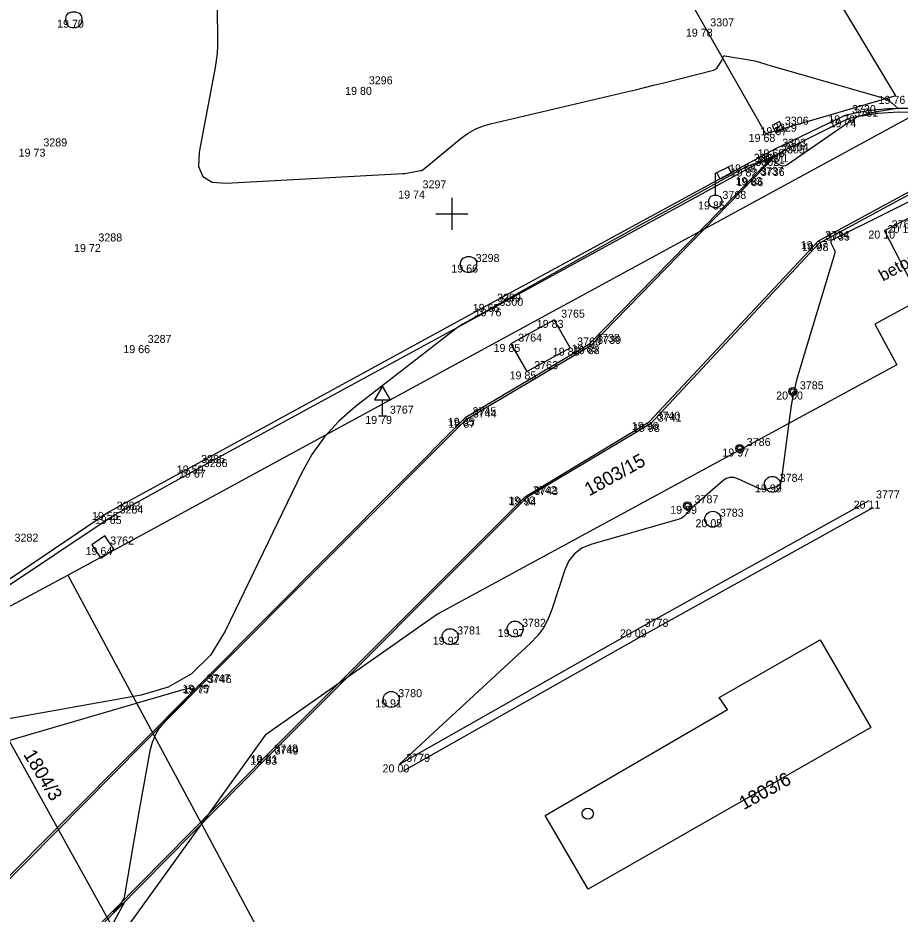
# Model space of a CAD drawing. Extents: x -702257 to -701487, y -1009871 to -1008841.
# Drawn here: x -702113.55 to -702085.99, y -1009721.88 to -1009693.87 of the extents above; entities that cross this region are included whole.
import ezdxf

# ---------------------------------------------------------------- set-up
doc = ezdxf.new("R2010")
doc.units = 0
for name, color, linetype in [('Ex_Major Contours', 7, 'Continuous'), ('Ex_Minor Contours', 7, 'Continuous'), ('Z_betonova_konstrukce', 7, 'Continuous'), ('Z_body', 7, 'Continuous'), ('Z_body_cisla', 7, 'Continuous'), ('Z_body_vysky_redukovane', 7, 'Continuous'), ('Z_dopravni_znacky', 7, 'Continuous'), ('Z_hektometricka_sit', 7, 'Continuous'), ('Z_katastr_cisla_pozemkova', 7, 'Continuous'), ('Z_katastr_cisla_stavebni', 7, 'Continuous'), ('Z_katastr_hranice', 7, 'Continuous'), ('Z_katastr_znacky_budov', 7, 'Continuous'), ('Z_komunikace', 7, 'Continuous'), ('Z_obruba', 7, 'Continuous'), ('Z_ploty', 7, 'Continuous'), ('Z_popisy', 7, 'Continuous'), ('Z_rozhranni', 7, 'Continuous'), ('Z_site_kanalizace_znaky', 7, 'Continuous'), ('Z_site_nerozlisene_znaky', 7, 'Continuous'), ('Z_site_vo_znaky', 7, 'Continuous'), ('Z_sloupek_kov', 7, 'Continuous'), ('Z_vdz_prechod', 7, 'Continuous'), ('Z_zelen_jednotliva', 7, 'Continuous')]:
    doc.layers.add(name, color=color, linetype=linetype)

# ---------------------------------------------------------------- blocks, each defined once
blk = doc.blocks.new('POINT_DISPLAY')
blk.add_line((0, 0), (0, 0))
blk = doc.blocks.new('Z620')
for p, q in [((-0.25, 0.05), (-0.23, 0.13)), ((-0.25, -0.05), (-0.25, 0.05)), ((-0.23, 0.13), (-0.17, 0.2)), ((-0.17, 0.2), (-0.05, 0.25)), ((-0.05, 0.25), (0.05, 0.25)), ((0.05, 0.25), (0.17, 0.2)), ((0.17, 0.2), (0.23, 0.13)), ((0.23, 0.13), (0.25, 0.05)), ((0.25, 0.05), (0.25, -0.05)), ((-0.2, -0.17), (-0.25, -0.05)), ((-0.13, -0.23), (-0.2, -0.17)), ((-0.05, -0.25), (-0.13, -0.23)), ((0.05, -0.25), (-0.05, -0.25)), ((0.13, -0.23), (0.05, -0.25)), ((0.2, -0.17), (0.13, -0.23)), ((0.25, -0.05), (0.2, -0.17))]:
    blk.add_line(p, q)
blk = doc.blocks.new('Z46260')
for p, q in [((0.13, 0.13), (-0.13, 0.13)), ((-0.13, 0.13), (-0.13, -0.13)), ((0.13, 0), (-0.13, 0)), ((0.13, -0.13), (0.13, 0.13)), ((-0.13, -0.13), (0.13, -0.13))]:
    blk.add_line(p, q)
blk = doc.blocks.new('Z15')
blk.add_circle((0, 0), 0.125)
blk = doc.blocks.new('Z10001')
blk.add_circle((0, 0), 0.25)
blk = doc.blocks.new('Z13')
for p, q in [((0, 0.88), (0.45, 1.1)), ((0, 0.2), (0, 0.88)), ((0.15, 0.7), (0.05, 0.9)), ((0.5, 0.88), (0.15, 0.7)), ((0.4, 1.07), (0.5, 0.88)), ((-0.2, 0.05), (-0.15, 0.15)), ((-0.2, -0.05), (-0.2, 0.05)), ((-0.15, 0.15), (-0.05, 0.2)), ((-0.05, 0.2), (0.05, 0.2)), ((0.05, 0.2), (0.15, 0.15)), ((0.15, 0.15), (0.2, 0.05)), ((0.2, 0.05), (0.2, -0.05)), ((-0.15, -0.15), (-0.2, -0.05)), ((-0.05, -0.2), (-0.15, -0.15)), ((0.05, -0.2), (-0.05, -0.2)), ((0.15, -0.15), (0.05, -0.2)), ((0.2, -0.05), (0.15, -0.15))]:
    blk.add_line(p, q)
blk = doc.blocks.new('Z608')
for p, q in [((0.25, 0.25), (-0.25, 0.25)), ((-0.25, 0.25), (-0.25, -0.25)), ((0.25, -0.25), (0.25, 0.25)), ((-0.25, -0.25), (0.25, -0.25))]:
    blk.add_line(p, q)
blk = doc.blocks.new('Z527')
for p, q in [((0, 0.93), (-0.25, 0.5)), ((0.25, 0.5), (0, 0.93)), ((-0.25, 0.5), (0.25, 0.5)), ((0, 0), (0, 0.5)), ((-0.13, 0), (0.13, 0))]:
    blk.add_line(p, q)

msp = doc.modelspace()

# ---------------------------------------------------------------- linework, layer by layer
at = {"layer": 'Ex_Major Contours'}
msp.add_lwpolyline([(-702084.852, -1009699.193), (-702088.099, -1009700.805), (-702088.132, -1009700.827), (-702088.149, -1009700.855), (-702088.151, -1009700.888), (-702088.138, -1009700.925), (-702088.055, -1009701.086), (-702088.038, -1009701.127), (-702088.03, -1009701.168), (-702088.031, -1009701.21), (-702088.04, -1009701.253), (-702089.125, -1009704.84), (-702089.225, -1009705.196), (-702089.311, -1009705.556), (-702089.381, -1009705.919), (-702089.437, -1009706.286), (-702089.709, -1009708.349), (-702089.726, -1009708.414), (-702089.759, -1009708.465), (-702089.806, -1009708.503), (-702089.869, -1009708.527), (-702090.15, -1009708.597), (-702090.219, -1009708.608), (-702090.288, -1009708.608), (-702090.355, -1009708.595), (-702090.421, -1009708.571), (-702091.059, -1009708.277), (-702091.184, -1009708.237), (-702091.304, -1009708.235), (-702091.419, -1009708.27), (-702091.528, -1009708.344), (-702092.418, -1009709.12), (-702092.457, -1009709.155), (-702092.496, -1009709.192), (-702092.534, -1009709.23), (-702092.571, -1009709.269), (-702092.715, -1009709.427), (-702092.753, -1009709.463), (-702092.795, -1009709.494), (-702092.84, -1009709.518), (-702092.89, -1009709.536), (-702095.648, -1009710.329), (-702095.932, -1009710.446), (-702096.164, -1009710.617), (-702096.343, -1009710.843), (-702096.469, -1009711.124), (-702096.866, -1009712.356), (-702096.983, -1009712.653), (-702097.134, -1009712.928), (-702097.32, -1009713.181), (-702097.54, -1009713.412), (-702101.64, -1009717.2)], dxfattribs=at)
at = {"layer": 'Ex_Minor Contours'}
for points in [[(-702107.333, -1009693.616), (-702107.318, -1009694.525), (-702107.32, -1009694.752), (-702107.333, -1009694.978), (-702107.358, -1009695.203), (-702107.395, -1009695.427), (-702107.896, -1009698.069), (-702107.916, -1009698.516), (-702107.781, -1009698.827), (-702107.49, -1009699.002), (-702107.045, -1009699.041), (-702101.522, -1009698.736), (-702101.466, -1009698.732), (-702101.411, -1009698.726), (-702101.355, -1009698.718), (-702101.3, -1009698.708), (-702100.977, -1009698.642), (-702100.971, -1009698.641), (-702100.966, -1009698.641), (-702100.952, -1009698.641), (-702100.946, -1009698.64), (-702100.93, -1009698.637), (-702100.923, -1009698.635), (-702100.911, -1009698.63), (-702100.907, -1009698.627), (-702100.905, -1009698.626), (-702099.699, -1009697.634), (-702099.49, -1009697.481), (-702099.269, -1009697.355), (-702099.035, -1009697.256), (-702098.787, -1009697.183), (-702094.534, -1009696.184), (-702094.254, -1009696.118), (-702093.973, -1009696.05), (-702093.693, -1009695.981), (-702093.413, -1009695.91), (-702091.817, -1009695.503), (-702091.778, -1009695.489), (-702091.744, -1009695.469), (-702091.714, -1009695.443), (-702091.689, -1009695.411), (-702091.573, -1009695.229), (-702091.563, -1009695.213), (-702091.554, -1009695.196), (-702091.547, -1009695.178), (-702091.54, -1009695.16), (-702091.516, -1009695.087), (-702091.509, -1009695.071), (-702091.498, -1009695.061), (-702091.484, -1009695.056), (-702091.466, -1009695.057), (-702090.582, -1009695.208), (-702090.531, -1009695.218), (-702090.48, -1009695.23), (-702090.429, -1009695.243), (-702090.379, -1009695.258), (-702090.179, -1009695.322), (-702090.129, -1009695.337), (-702090.079, -1009695.353), (-702090.028, -1009695.368), (-702089.978, -1009695.383), (-702086.382, -1009696.418), (-702086.378, -1009696.42), (-702086.373, -1009696.423), (-702086.357, -1009696.437), (-702086.329, -1009696.462), (-702086.321, -1009696.469), (-702086.267, -1009696.515), (-702086.24, -1009696.538), (-702086.044, -1009696.701), (-702086.04, -1009696.705), (-702086.044, -1009696.705), (-702086.292, -1009696.739), (-702086.319, -1009696.742), (-702086.364, -1009696.748), (-702086.373, -1009696.749), (-702086.382, -1009696.75), (-702086.39, -1009696.752), (-702086.399, -1009696.753), (-702086.481, -1009696.768), (-702086.524, -1009696.776), (-702086.657, -1009696.8), (-702086.683, -1009696.805), (-702086.71, -1009696.81), (-702086.737, -1009696.816), (-702086.763, -1009696.822), (-702086.905, -1009696.855), (-702086.942, -1009696.863), (-702087.004, -1009696.878), (-702087.017, -1009696.881), (-702087.029, -1009696.884), (-702087.041, -1009696.887), (-702087.054, -1009696.89), (-702087.306, -1009696.962), (-702087.31, -1009696.963), (-702087.313, -1009696.964), (-702087.317, -1009696.966), (-702087.321, -1009696.968), (-702087.339, -1009696.978), (-702087.349, -1009696.985), (-702087.602, -1009697.149), (-702087.646, -1009697.178), (-702087.689, -1009697.206), (-702087.732, -1009697.235), (-702087.774, -1009697.264), (-702089.532, -1009698.476), (-702089.579, -1009698.501), (-702089.626, -1009698.51), (-702089.674, -1009698.505), (-702089.723, -1009698.486), (-702089.997, -1009698.334), (-702090.007, -1009698.33), (-702090.017, -1009698.328), (-702090.027, -1009698.33), (-702090.038, -1009698.334), (-702090.084, -1009698.359), (-702090.091, -1009698.363), (-702090.098, -1009698.367), (-702090.104, -1009698.371), (-702090.111, -1009698.376), (-702090.137, -1009698.394), (-702090.143, -1009698.397), (-702090.149, -1009698.398), (-702090.155, -1009698.396), (-702090.161, -1009698.392), (-702090.206, -1009698.345), (-702090.216, -1009698.337), (-702090.226, -1009698.333), (-702090.238, -1009698.332), (-702090.25, -1009698.334), (-702090.63, -1009698.468), (-702090.697, -1009698.493), (-702090.763, -1009698.52), (-702090.827, -1009698.551), (-702090.891, -1009698.584), (-702093.235, -1009699.87), (-702093.647, -1009700.096), (-702094.058, -1009700.323), (-702094.469, -1009700.551), (-702094.879, -1009700.779), (-702098.61, -1009702.862), (-702098.678, -1009702.899), (-702098.745, -1009702.937), (-702098.813, -1009702.975), (-702098.881, -1009703.013), (-702099.167, -1009703.172), (-702099.227, -1009703.205), (-702099.288, -1009703.239), (-702099.347, -1009703.273), (-702099.407, -1009703.307), (-702099.647, -1009703.442), (-702099.706, -1009703.477), (-702099.764, -1009703.514), (-702099.82, -1009703.553), (-702099.875, -1009703.594), (-702103.017, -1009706.03), (-702103.528, -1009706.475), (-702103.978, -1009706.969), (-702104.367, -1009707.512), (-702104.695, -1009708.105), (-702107.076, -1009713.042), (-702107.542, -1009713.792), (-702108.135, -1009714.374), (-702108.855, -1009714.789), (-702109.703, -1009715.035), (-702115.021, -1009715.984)], [(-702115.35, -1009716.896), (-702108.389, -1009714.859), (-702108.189, -1009714.818), (-702108.098, -1009714.844), (-702108.116, -1009714.936), (-702108.244, -1009715.095), (-702108.972, -1009715.866), (-702109.137, -1009716.067), (-702109.268, -1009716.285), (-702109.365, -1009716.52), (-702109.429, -1009716.773), (-702109.73, -1009718.45), (-702109.783, -1009718.749), (-702109.836, -1009719.047), (-702109.888, -1009719.346), (-702109.939, -1009719.644), (-702110.222, -1009721.293), (-702110.239, -1009721.363), (-702110.265, -1009721.427), (-702110.301, -1009721.487), (-702110.346, -1009721.543), (-702110.545, -1009721.756), (-702110.582, -1009721.796), (-702110.592, -1009721.811), (-702110.577, -1009721.801), (-702110.535, -1009721.766), (-702110.314, -1009721.57), (-702110.27, -1009721.536), (-702110.248, -1009721.53), (-702110.25, -1009721.552), (-702110.274, -1009721.602), (-702110.942, -1009722.829)]]:
    msp.add_lwpolyline(points, dxfattribs=at)
at = {"layer": 'Z_betonova_konstrukce'}
for centre in [(-702089.34, -1009705.55), (-702091, -1009707.33), (-702092.63, -1009709.12)]:
    msp.add_circle(centre, 0.08, dxfattribs=at)
at = {"layer": 'Z_hektometricka_sit'}
for p, q in [((-702100, -1009699.5), (-702100, -1009700.5)), ((-702100.5, -1009700), (-702099.5, -1009700))]:
    msp.add_line(p, q, dxfattribs=at)
at = {"layer": 'Z_katastr_hranice'}
for p, q in [((-702111.99, -1009711.29), (-702084.75, -1009696.47)), ((-702080.15, -1009699.84), (-702086.78, -1009703.44)), ((-702086.78, -1009703.44), (-702086.09, -1009704.72)), ((-702086.09, -1009704.72), (-702100.44, -1009712.51)), ((-702115.63, -1009713.22), (-702111.99, -1009711.29)), ((-702111.99, -1009711.29), (-702107.82, -1009719.06)), ((-702100.44, -1009712.51), (-702105.83, -1009716.29)), ((-702110.4, -1009722.64), (-702115.63, -1009713.22)), ((-702091.64, -1009715.11), (-702088.49, -1009713.31)), ((-702088.49, -1009713.31), (-702086.9, -1009716.05)), ((-702091.38, -1009715.48), (-702091.64, -1009715.11)), ((-702097.08, -1009718.8), (-702091.38, -1009715.48)), ((-702086.9, -1009716.05), (-702095.73, -1009721.1)), ((-702105.83, -1009716.29), (-702107.82, -1009719.06)), ((-702095.73, -1009721.1), (-702097.08, -1009718.8)), ((-702107.82, -1009719.06), (-702110.4, -1009722.64)), ((-702107.82, -1009719.06), (-702098.87, -1009735.75))]:
    msp.add_line(p, q, dxfattribs=at)
at = {"layer": 'Z_katastr_znacky_budov'}
msp.add_circle((-702095.747, -1009718.739), 0.175, dxfattribs=at)
at = {"layer": 'Z_komunikace'}
for p, q in [((-702087.71, -1009696.92), (-702089.9, -1009697.98)), ((-702089.9, -1009697.98), (-702090.79, -1009698.45)), ((-702090.79, -1009698.45), (-702098.8, -1009702.81)), ((-702098.8, -1009702.81), (-702108.05, -1009707.86)), ((-702108.05, -1009707.86), (-702110.7, -1009709.31)), ((-702110.7, -1009709.31), (-702117.54, -1009713.9))]:
    msp.add_line(p, q, dxfattribs=at)
msp.add_ellipse((-702085.925, -1009704.127), major_axis=(-6.059, 4.296), ratio=0.999043, start_param=4.841691, end_param=5.571482, dxfattribs=at)
at = {"layer": 'Z_obruba'}
for p, q in [((-702089.82, -1009698.12), (-702087.65, -1009697.04)), ((-702089.93, -1009698.18), (-702090.74, -1009698.58)), ((-702089.93, -1009698.18), (-702090.59, -1009698.85)), ((-702090.56, -1009698.88), (-702089.82, -1009698.12)), ((-702083.63, -1009698.18), (-702088.55, -1009700.85)), ((-702088.52, -1009700.91), (-702083.62, -1009698.27)), ((-702098.74, -1009702.95), (-702090.74, -1009698.58)), ((-702095.71, -1009704.08), (-702090.59, -1009698.85)), ((-702090.56, -1009698.88), (-702095.67, -1009704.13)), ((-702088.55, -1009700.85), (-702093.83, -1009706.5)), ((-702093.79, -1009706.56), (-702088.52, -1009700.91)), ((-702107.98, -1009707.99), (-702098.74, -1009702.95)), ((-702095.71, -1009704.08), (-702099.58, -1009706.37)), ((-702095.67, -1009704.13), (-702099.56, -1009706.43)), ((-702099.58, -1009706.37), (-702107.88, -1009714.71)), ((-702107.84, -1009714.74), (-702099.56, -1009706.43)), ((-702097.69, -1009708.83), (-702093.83, -1009706.5)), ((-702093.79, -1009706.56), (-702097.65, -1009708.86)), ((-702110.61, -1009709.44), (-702107.98, -1009707.99)), ((-702105.78, -1009716.91), (-702097.69, -1009708.83)), ((-702097.65, -1009708.86), (-702105.75, -1009716.96)), ((-702117.46, -1009714.02), (-702110.61, -1009709.44)), ((-702107.88, -1009714.71), (-702114.64, -1009721.5)), ((-702114.57, -1009721.54), (-702107.84, -1009714.74)), ((-702105.78, -1009716.91), (-702112.48, -1009723.7)), ((-702112.43, -1009723.73), (-702105.75, -1009716.96))]:
    msp.add_line(p, q, dxfattribs=at)
msp.add_ellipse((-702085.912, -1009703.852), major_axis=(-5.916, 3.802), ratio=0.999175, start_param=4.791004, end_param=5.532886, dxfattribs=at)
at = {"layer": 'Z_ploty'}
for p, q in [((-702086.96, -1009708.96), (-702094.2, -1009712.98)), ((-702086.84, -1009709.18), (-702094.08, -1009713.2)), ((-702094.2, -1009712.98), (-702101.64, -1009717.2)), ((-702094.08, -1009713.2), (-702101.52, -1009717.41))]:
    msp.add_line(p, q, dxfattribs=at)
at = {"layer": 'Z_rozhranni'}
for p, q in [((-702086.48, -1009700.52), (-702084.89, -1009699.7)), ((-702085.48, -1009702.45), (-702086.48, -1009700.52))]:
    msp.add_line(p, q, dxfattribs=at)
at = {"layer": 'Z_site_nerozlisene_znaky'}
for p, q in [((-702096.8, -1009703.31), (-702098.15, -1009704.06)), ((-702096.3, -1009704.18), (-702096.8, -1009703.31)), ((-702098.15, -1009704.06), (-702097.65, -1009704.92)), ((-702097.65, -1009704.92), (-702096.3, -1009704.18))]:
    msp.add_line(p, q, dxfattribs=at)
at = {"layer": 'Z_vdz_prechod'}
for p, q in [((-702086.12, -1009696.31), (-702090.46, -1009689.07)), ((-702090.18, -1009697.5), (-702093.87, -1009691.01)), ((-702086.12, -1009696.31), (-702090.18, -1009697.5))]:
    msp.add_line(p, q, dxfattribs=at)

# ---------------------------------------------------------------- block references
at = {"layer": 'Z_body'}
for p in [(-702111.81, -1009693.93), (-702092.14, -1009694.21), (-702102.81, -1009696.03), (-702086.12, -1009696.31), (-702087.71, -1009696.92), (-702087.65, -1009697.04), (-702089.81, -1009697.29), (-702090.18, -1009697.5), (-702112.99, -1009697.96), (-702089.9, -1009697.98), (-702089.93, -1009698.18), (-702089.82, -1009698.12), (-702090.79, -1009698.45), (-702090.74, -1009698.58), (-702090.59, -1009698.85), (-702090.56, -1009698.88), (-702101.13, -1009699.27), (-702091.76, -1009699.61), (-702086.48, -1009700.52), (-702111.26, -1009700.94), (-702088.55, -1009700.85), (-702088.52, -1009700.91), (-702099.47, -1009701.58), (-702098.8, -1009702.81), (-702098.74, -1009702.95), (-702096.8, -1009703.31), (-702109.72, -1009704.1), (-702098.15, -1009704.06), (-702096.3, -1009704.18), (-702095.71, -1009704.08), (-702095.67, -1009704.13), (-702097.65, -1009704.92), (-702089.34, -1009705.55), (-702102.16, -1009706.31), (-702099.58, -1009706.37), (-702099.56, -1009706.43), (-702093.83, -1009706.5), (-702093.79, -1009706.56), (-702091, -1009707.33), (-702108.05, -1009707.86), (-702107.98, -1009707.99), (-702089.98, -1009708.45), (-702097.69, -1009708.83), (-702097.65, -1009708.86), (-702086.96, -1009708.96), (-702092.63, -1009709.12), (-702110.7, -1009709.31), (-702110.61, -1009709.44), (-702091.84, -1009709.54), (-702110.9, -1009710.41), (-702098.02, -1009712.97), (-702094.2, -1009712.98), (-702100.05, -1009713.21), (-702107.88, -1009714.71), (-702107.84, -1009714.74), (-702101.89, -1009715.17), (-702105.78, -1009716.91), (-702105.75, -1009716.96), (-702101.64, -1009717.2)]:
    msp.add_blockref('POINT_DISPLAY', p, dxfattribs=at)
at = {"layer": 'Z_dopravni_znacky'}
msp.add_blockref('Z527', (-702102.16, -1009706.31), dxfattribs=at)
at = {"layer": 'Z_site_kanalizace_znaky'}
for p in [(-702111.81, -1009693.93), (-702099.47, -1009701.58)]:
    msp.add_blockref('Z620', p, dxfattribs=at)
at = {"layer": 'Z_site_kanalizace_znaky', "rotation": 26.999999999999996}
msp.add_blockref('Z46260', (-702089.81, -1009697.29), dxfattribs=at)
at = {"layer": 'Z_site_nerozlisene_znaky', "rotation": 34.199999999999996}
msp.add_blockref('Z608', (-702110.9, -1009710.41), dxfattribs=at)
at = {"layer": 'Z_site_vo_znaky'}
msp.add_blockref('Z13', (-702091.76, -1009699.61), dxfattribs=at)
at = {"layer": 'Z_sloupek_kov'}
for p in [(-702089.34, -1009705.55), (-702091, -1009707.33), (-702092.63, -1009709.12)]:
    msp.add_blockref('Z15', p, dxfattribs=at)
at = {"layer": 'Z_zelen_jednotliva'}
for p in [(-702089.98, -1009708.45), (-702091.84, -1009709.54), (-702098.02, -1009712.97), (-702100.05, -1009713.21), (-702101.89, -1009715.17)]:
    msp.add_blockref('Z10001', p, dxfattribs=at)

# ---------------------------------------------------------------- texts
at = {"layer": 'Z_body_cisla'}
for s, p in [('3307', (-702091.92, -1009694.14)), ('3296', (-702102.59, -1009695.95)), ('3730', (-702087.49, -1009696.85)), ('3731', (-702087.42, -1009696.96)), ('3329', (-702089.96, -1009697.43)), ('3306', (-702089.59, -1009697.21)), ('3289', (-702112.76, -1009697.89)), ('3303', (-702089.67, -1009697.9)), ('3305', (-702089.71, -1009698.11)), ('3304', (-702089.59, -1009698.04)), ('3301', (-702090.56, -1009698.37)), ('3302', (-702090.51, -1009698.5)), ('3737', (-702090.37, -1009698.78)), ('3736', (-702090.34, -1009698.81)), ('3297', (-702100.91, -1009699.2)), ('3768', (-702091.54, -1009699.53)), ('3769', (-702086.25, -1009700.45)), ('3734', (-702088.33, -1009700.78)), ('3288', (-702111.04, -1009700.86)), ('3735', (-702088.3, -1009700.83)), ('3298', (-702099.25, -1009701.5)), ('3299', (-702098.58, -1009702.74)), ('3300', (-702098.51, -1009702.87)), ('3765', (-702096.58, -1009703.24)), ('3287', (-702109.5, -1009704.03)), ('3764', (-702097.92, -1009703.99)), ('3766', (-702096.08, -1009704.11)), ('4738', (-702095.49, -1009704)), ('3739', (-702095.45, -1009704.06)), ('3763', (-702097.42, -1009704.85)), ('3785', (-702089.12, -1009705.48)), ('3767', (-702101.93, -1009706.24)), ('3745', (-702099.35, -1009706.29)), ('3744', (-702099.34, -1009706.36)), ('3740', (-702093.6, -1009706.43)), ('3741', (-702093.56, -1009706.49)), ('3786', (-702090.78, -1009707.25)), ('3285', (-702107.83, -1009707.78)), ('3286', (-702107.75, -1009707.91)), ('3784', (-702089.75, -1009708.37)), ('3742', (-702097.46, -1009708.75)), ('3743', (-702097.42, -1009708.78)), ('3777', (-702086.74, -1009708.89)), ('3787', (-702092.41, -1009709.04)), ('3283', (-702110.47, -1009709.24)), ('3284', (-702110.38, -1009709.36)), ('3783', (-702091.62, -1009709.46)), ('3282', (-702113.66, -1009710.24)), ('3762', (-702110.67, -1009710.33)), ('3781', (-702099.83, -1009713.14)), ('3782', (-702097.8, -1009712.9)), ('3778', (-702093.97, -1009712.9)), ('3747', (-702107.66, -1009714.64)), ('3746', (-702107.62, -1009714.66)), ('3780', (-702101.67, -1009715.1)), ('3748', (-702105.55, -1009716.83)), ('3749', (-702105.53, -1009716.89)), ('3779', (-702101.42, -1009717.12))]:
    msp.add_text(s, height=0.25, dxfattribs=at).set_placement(p)
at = {"layer": 'Z_body_vysky_redukovane'}
for s, p in [('19 70', (-702112.331, -1009694.18)), ('19 78', (-702092.682, -1009694.46)), ('19 80', (-702103.331, -1009696.28)), ('19 76', (-702086.662, -1009696.56)), ('19 70', (-702088.231, -1009697.17)), ('19 74', (-702088.192, -1009697.29)), ('19 67', (-702090.352, -1009697.54)), ('19 68', (-702090.722, -1009697.75)), ('19 73', (-702113.532, -1009698.21)), ('19 68', (-702090.442, -1009698.23)), ('19 71', (-702090.43, -1009698.43)), ('19 71', (-702090.32, -1009698.37)), ('19 68', (-702091.332, -1009698.7)), ('19 82', (-702091.282, -1009698.83)), ('19 83', (-702091.132, -1009699.1)), ('19 86', (-702091.102, -1009699.13)), ('19 74', (-702101.672, -1009699.52)), ('19 85', (-702092.302, -1009699.86)), ('20 10', (-702086.98, -1009700.77)), ('20 11', (-702086.379, -1009700.6)), ('19 97', (-702089.092, -1009701.1)), ('19 72', (-702111.802, -1009701.19)), ('19 98', (-702089.062, -1009701.16)), ('19 66', (-702100.012, -1009701.83)), ('19 65', (-702099.342, -1009703.06)), ('19 76', (-702099.282, -1009703.2)), ('19 83', (-702097.342, -1009703.56)), ('19 66', (-702110.262, -1009704.35)), ('19 85', (-702098.692, -1009704.31)), ('19 85', (-702096.842, -1009704.43)), ('19 85', (-702096.252, -1009704.33)), ('19 88', (-702096.212, -1009704.38)), ('19 85', (-702098.192, -1009705.17)), ('20 00', (-702089.861, -1009705.8)), ('19 79', (-702102.702, -1009706.56)), ('19 85', (-702100.122, -1009706.62)), ('19 87', (-702100.102, -1009706.68)), ('19 96', (-702094.372, -1009706.75)), ('19 98', (-702094.332, -1009706.81)), ('19 97', (-702091.542, -1009707.58)), ('19 59', (-702108.592, -1009708.11)), ('19 67', (-702108.522, -1009708.24)), ('19 99', (-702090.522, -1009708.7)), ('19 93', (-702098.232, -1009709.08)), ('19 94', (-702098.192, -1009709.11)), ('20 11', (-702087.439, -1009709.21)), ('19 99', (-702093.172, -1009709.37)), ('19 55', (-702111.242, -1009709.56)), ('19 65', (-702111.152, -1009709.69)), ('20 05', (-702092.382, -1009709.79)), ('19 64', (-702111.442, -1009710.66)), ('19 97', (-702098.562, -1009713.22)), ('20 09', (-702094.742, -1009713.23)), ('19 92', (-702100.592, -1009713.46)), ('19 75', (-702108.422, -1009714.96)), ('19 77', (-702108.382, -1009714.99)), ('19 91', (-702102.39, -1009715.42)), ('19 83', (-702106.292, -1009717.21)), ('19 81', (-702106.28, -1009717.16)), ('20 00', (-702102.161, -1009717.45))]:
    msp.add_text(s, height=0.25, dxfattribs=at).set_placement(p)
at = {"layer": 'Z_katastr_cisla_pozemkova'}
for s, rotation, p in [('1803/15', 29, (-702095.701, -1009708.829)), ('1804/3', 301, (-702113.399, -1009716.891))]:
    msp.add_text(s, height=0.425, rotation=rotation, dxfattribs=at).set_placement(p)
at = {"layer": 'Z_katastr_cisla_stavebni'}
msp.add_text('1803/6', height=0.425, rotation=29, dxfattribs=at).set_placement((-702090.871, -1009718.632))
at = {"layer": 'Z_popisy'}
msp.add_text('beton', height=0.38, rotation=28.8, dxfattribs=at).set_placement((-702086.523, -1009702.118))

doc.saveas('drawing.dxf')
